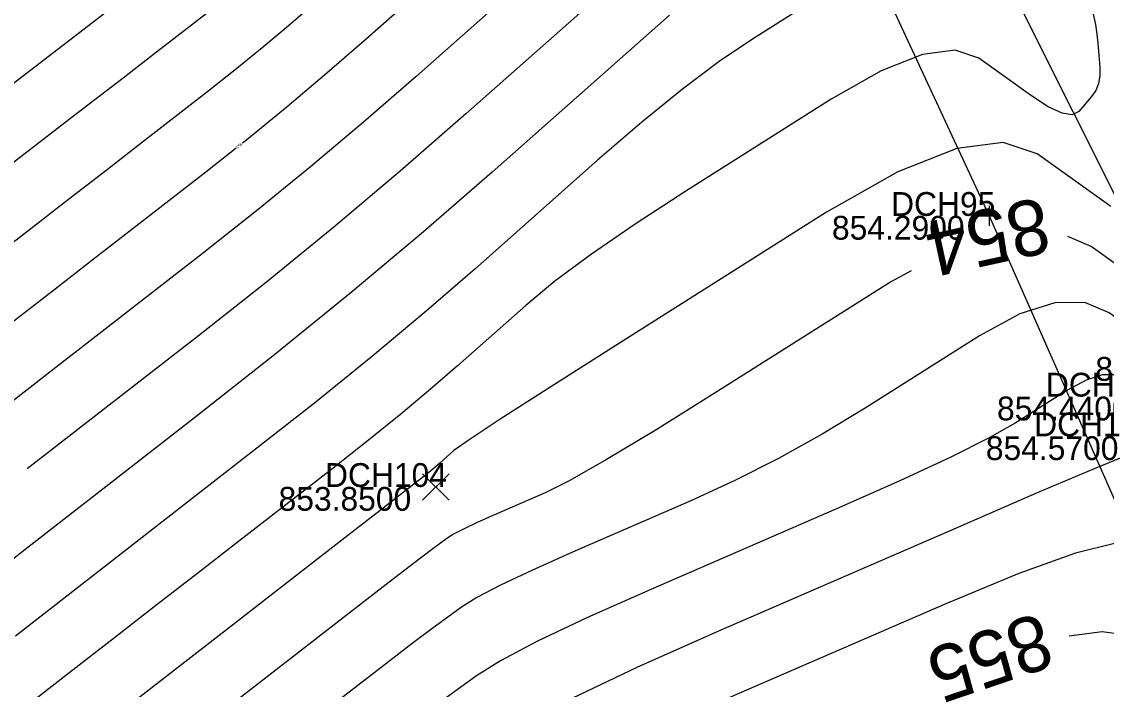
# Model space of a CAD drawing. Extents: x 1654928 to 1810050, y 486881 to 626330.
# Drawn here: x 1801428 to 1801482.8, y 489650.4 to 489684 of the extents above; entities that cross this region are included whole.
import ezdxf

# ---------------------------------------------------------------- set-up
doc = ezdxf.new("R2010")
doc.units = 0
for name, color, linetype in [('DT_X_Contour_Major', 7, 'Continuous'), ('DT_X_Contour_Minor', 7, 'Continuous'), ('RW_X_Esmt_SH', 7, 'Continuous'), ('SV_X_Occupation_Line', 7, 'Continuous'), ('SV_X_Random_Point', 7, 'Continuous'), ('SV_X_Shot_Marker', 7, 'Continuous'), ('SV_X_Text_Elevation', 7, 'Continuous'), ('SV_X_Text_Name', 7, 'Continuous')]:
    doc.layers.add(name, color=color, linetype=linetype)

msp = doc.modelspace()

# ---------------------------------------------------------------- linework, layer by layer
at = {"layer": 'DT_X_Contour_Major'}
for points in [[(1801443.034, 489696.692), (1801437.883, 489688.83), (1801419.343, 489674.574), (1801415.636, 489671.737), (1801412.458, 489669.335), (1801409.812, 489667.368), (1801407.696, 489665.836), (1801402.76, 489662.331), (1801400.873, 489661.154), (1801398.913, 489660.252), (1801396.88, 489659.625), (1801394.775, 489659.273), (1801389.065, 489658.701), (1801386.962, 489658.363), (1801384.937, 489657.778), (1801382.989, 489656.946), (1801381.119, 489655.867), (1801376.236, 489652.66), (1801374.448, 489651.569), (1801372.743, 489650.703), (1801371.123, 489650.059), (1801369.588, 489649.64), (1801362.619, 489648.206)], [(1801459.21, 489687.139), (1801450.432, 489679.372), (1801447.119, 489676.488), (1801443.765, 489673.661), (1801440.37, 489670.89), (1801436.933, 489668.176), (1801428.29, 489661.464)], [(1801486.55, 489669.424), (1801481.996, 489672.691), (1801480.817, 489673.19)], [(1801472.904, 489671.461), (1801471.911, 489670.926), (1801463.018, 489665.305), (1801459.98, 489663.408), (1801457.537, 489661.935), (1801455.687, 489660.884), (1801454.431, 489660.256), (1801451.875, 489659.146), (1801451.007, 489658.76), (1801450.317, 489658.433), (1801449.807, 489658.167), (1801449.476, 489657.96), (1801448.833, 489657.489), (1801448.146, 489656.965), (1801446.567, 489655.746), (1801444.095, 489653.832), (1801430.572, 489643.341)], [(1801491.749, 489649.836), (1801490.721, 489650.553), (1801489.523, 489651.178), (1801488.155, 489651.712), (1801484.278, 489653.014), (1801482.547, 489653.242), (1801480.885, 489653.029)]]:
    msp.add_lwpolyline(points, dxfattribs=at)
at = {"layer": 'DT_X_Contour_Minor'}
for points in [[(1801450.679, 489687.816), (1801445.412, 489683.155), (1801443.425, 489681.425), (1801441.412, 489679.728), (1801439.375, 489678.066), (1801439.168, 489677.902)], [(1801454.945, 489687.478), (1801447.922, 489681.264), (1801445.272, 489678.956), (1801442.589, 489676.695), (1801439.872, 489674.478), (1801437.123, 489672.307), (1801429.746, 489666.578), (1801427.145, 489664.559)], [(1801469.106, 489685.807), (1801464.893, 489683.145), (1801463.22, 489682.014), (1801461.361, 489680.618), (1801459.316, 489678.958), (1801457.084, 489677.034), (1801450.884, 489671.548), (1801448.434, 489669.426), (1801445.735, 489667.172), (1801442.787, 489664.788), (1801439.588, 489662.273), (1801427.698, 489653.038)], [(1801442.903, 489685.047), (1801441.577, 489683.893), (1801440.236, 489682.762), (1801438.878, 489681.654), (1801437.503, 489680.568), (1801433.815, 489677.704), (1801432.265, 489676.503), (1801430.384, 489675.05), (1801428.171, 489673.344), (1801425.625, 489671.386)], [(1801437.693, 489684.699), (1801435.849, 489683.267), (1801434.826, 489682.476), (1801433.14, 489681.176), (1801430.792, 489679.369), (1801418.869, 489670.2)], [(1801460.713, 489684.357), (1801451.758, 489676.433), (1801448.301, 489673.43), (1801444.646, 489670.365), (1801440.793, 489667.237), (1801436.743, 489664.046), (1801419.36, 489650.546)], [(1801482.097, 489684.394), (1801482.203, 489683.885), (1801482.28, 489683.399), (1801482.33, 489682.936), (1801482.426, 489681.73), (1801482.427, 489681.298), (1801482.358, 489680.908), (1801482.221, 489680.559), (1801482.014, 489680.25), (1801481.369, 489679.484), (1801481.035, 489679.32), (1801480.518, 489679.403), (1801479.816, 489679.733), (1801478.931, 489680.311), (1801476.325, 489682.181), (1801475.126, 489682.577), (1801473.484, 489682.364), (1801471.399, 489681.54), (1801468.871, 489680.107), (1801461.538, 489675.472), (1801458.97, 489673.809), (1801456.767, 489672.294), (1801454.929, 489670.928), (1801453.455, 489669.711), (1801450.011, 489666.663), (1801448.65, 489665.484), (1801447.15, 489664.232), (1801445.512, 489662.907), (1801443.735, 489661.51), (1801438.812, 489657.687), (1801436.902, 489656.203), (1801434.863, 489654.621), (1801432.696, 489652.939), (1801430.4, 489651.157), (1801424.106, 489646.274)], [(1801482.977, 489674.697), (1801479.262, 489677.363), (1801477.553, 489677.928), (1801475.212, 489677.624), (1801472.24, 489676.45), (1801468.636, 489674.407), (1801458.183, 489667.8), (1801454.72, 489665.604), (1801452.173, 489663.969), (1801450.542, 489662.897), (1801449.826, 489662.388), (1801449.137, 489661.778), (1801448.865, 489661.542), (1801448.565, 489661.292), (1801448.237, 489661.027), (1801447.882, 489660.748), (1801446.106, 489659.368), (1801444.469, 489658.099), (1801441.988, 489656.173), (1801438.662, 489653.593), (1801428.666, 489645.837)], [(1801438.838, 489677.642), (1801437.313, 489676.438), (1801431.78, 489672.141), (1801429.705, 489670.531), (1801427.628, 489668.924), (1801425.549, 489667.32), (1801423.469, 489665.718), (1801417.92, 489661.451), (1801415.715, 489659.779), (1801413.263, 489657.961), (1801410.563, 489655.998), (1801407.615, 489653.889), (1801399.425, 489648.073)], [(1801488.056, 489665.46), (1801487.905, 489665.598), (1801486.925, 489666.409), (1801485.859, 489667.209), (1801482.903, 489669.33), (1801481.663, 489669.855), (1801480.158, 489669.839), (1801478.39, 489669.282), (1801476.357, 489668.184), (1801470.584, 489664.535), (1801468.411, 489663.217), (1801466.219, 489661.997), (1801464.009, 489660.877), (1801461.782, 489659.856), (1801455.818, 489657.265), (1801453.791, 489656.363), (1801452.182, 489655.602), (1801450.991, 489654.98), (1801450.22, 489654.498), (1801448.719, 489653.398), (1801447.798, 489652.705), (1801446.161, 489651.45), (1801443.807, 489649.633)], [(1801483.241, 489666.21), (1801482.549, 489666.202), (1801481.737, 489665.947), (1801480.803, 489665.442), (1801478.151, 489663.766), (1801476.841, 489663.025), (1801474.901, 489662.059), (1801472.332, 489660.87), (1801469.132, 489659.455), (1801459.76, 489655.384), (1801456.575, 489653.967), (1801454.046, 489652.77), (1801452.176, 489651.793), (1801450.963, 489651.035), (1801448.605, 489649.308)], [(1801497.063, 489648.999), (1801494.869, 489651.39), (1801493.996, 489652.345), (1801493.021, 489653.415), (1801491.944, 489654.601), (1801490.767, 489655.903), (1801487.491, 489659.529), (1801486.403, 489660.723), (1801485.597, 489661.585), (1801485.073, 489662.117), (1801484.831, 489662.316), (1801484.561, 489662.407), (1801483.905, 489662.191), (1801482.14, 489661.473), (1801479.267, 489660.254), (1801475.286, 489658.534), (1801463.19, 489653.28), (1801459.07, 489651.445), (1801455.783, 489649.883)], [(1801494.783, 489649.037), (1801490.935, 489653.297), (1801489.575, 489654.728), (1801488.381, 489655.824), (1801487.354, 489656.586), (1801486.493, 489657.014), (1801484.419, 489657.711), (1801483.226, 489657.716), (1801481.201, 489657.211), (1801478.344, 489656.195), (1801474.656, 489654.667), (1801463.712, 489649.913)]]:
    msp.add_lwpolyline(points, dxfattribs=at)
at = {"layer": 'RW_X_Esmt_SH'}
msp.add_line((1801533.563, 489574.54), (1801308.538, 490024.454), dxfattribs=at)
at = {"layer": 'SV_X_Occupation_Line'}
msp.add_lwpolyline([(1801317.131, 489768.671), (1801358.983, 489768.588), (1801397.909, 489769.246), (1801416.492, 489765.323), (1801429.827, 489757.814), (1801441.541, 489745.071), (1801453.578, 489722.317), (1801464.849, 489700.041), (1801476.834, 489674.228), (1801497.657, 489627.098)], dxfattribs=at)
at = {"layer": 'SV_X_Random_Point'}
for p, q in [((1801448.252, 489659.889), (1801449.585, 489661.224)), ((1801448.252, 489661.224), (1801449.585, 489659.889))]:
    msp.add_line(p, q, dxfattribs=at)
at = {"layer": 'SV_X_Shot_Marker'}
for p, q in [((1801476.834, 489674.728), (1801476.834, 489673.728)), ((1801476.334, 489674.228), (1801477.334, 489674.228)), ((1801476.834, 489674.228), (1801476.834, 489674.228))]:
    msp.add_line(p, q, dxfattribs=at)

# ---------------------------------------------------------------- texts
at = {"layer": 'DT_X_Contour_Major'}
for s, rotation, p in [('854', 192.3226, (1801479.533, 489675.193)), ('855', 198.7639, (1801479.413, 489654.26))]:
    msp.add_text(s, height=2.8, rotation=rotation, dxfattribs=at).set_placement(p)
at = {"layer": 'DT_X_Contour_Minor'}
msp.add_text('853', height=0.14, rotation=218.2941, dxfattribs=at).set_placement((1801439.084, 489677.926))
at = {"layer": 'SV_X_Text_Elevation'}
for s, p in [('854.2900', (1801468.907, 489673.028)), ('853.9800', (1801482.198, 489665.909)), ('854.4400', (1801477.237, 489663.913)), ('854.5700', (1801476.674, 489661.912)), ('853.8500', (1801440.982, 489659.357))]:
    msp.add_text(s, height=1.2, dxfattribs=at).set_placement(p)
at = {"layer": 'SV_X_Text_Name'}
for s, p in [('DCH95', (1801471.893, 489674.228)), ('DCH128', (1801479.704, 489665.113)), ('DCH127', (1801479.112, 489663.112)), ('DCH104', (1801443.326, 489660.557))]:
    msp.add_text(s, height=1.2, dxfattribs=at).set_placement(p)

doc.saveas('drawing.dxf')
